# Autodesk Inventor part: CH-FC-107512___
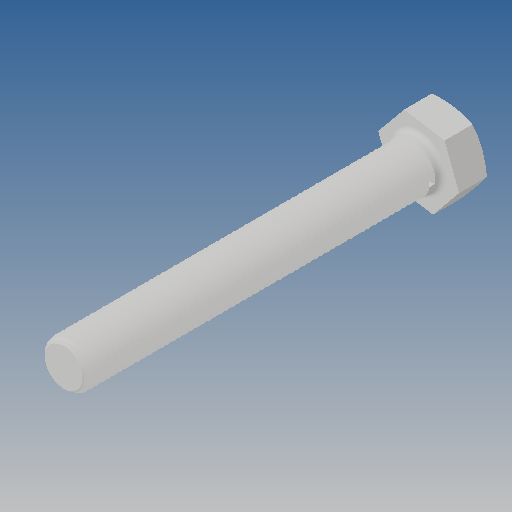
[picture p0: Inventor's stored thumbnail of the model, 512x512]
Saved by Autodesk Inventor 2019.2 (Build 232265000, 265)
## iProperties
Created: 2010-06
Part Number: CH-FC-107512___
Material: Ogólny
Document SubType Name: Modeling
Designer: CADENGINEERING4
Density: 1 g/cm^3
Appearance: Domyślna
Author: CADENGINEERING4
Revision Number: ANY
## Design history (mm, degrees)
feature "NONE"
node "Bryła1"
